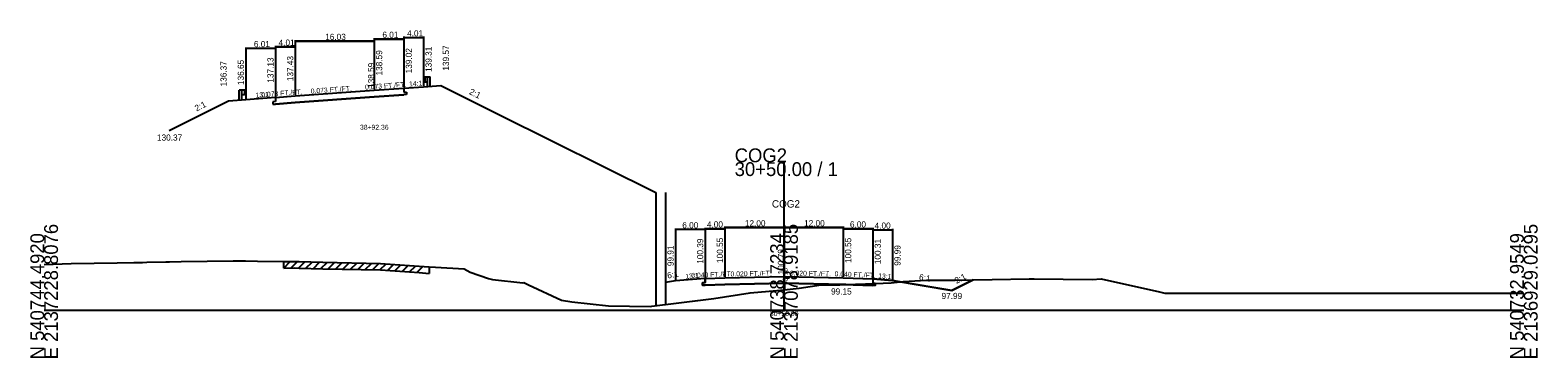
# Model space of a CAD drawing. Extents: x -13397 to 2303, y -10 to 39059.
# Drawn here: x 997.2 to 1302.8, y 990.3 to 1056.8 of the extents above; entities that cross this region are included whole.
import ezdxf

# ---------------------------------------------------------------- set-up
doc = ezdxf.new("R2010")
doc.units = 0
for name, color, linetype in [('Level 20', 7, 'Continuous'), ('Level 5', 7, 'Continuous'), ('Level 53', 7, 'Continuous'), ('Level 54', 7, 'Continuous'), ('Level 55', 7, 'Continuous'), ('Level 7', 7, 'Continuous'), ('RD_GPK_XS_Cell', 7, 'Continuous'), ('RD_XS_EwShp', 7, 'Continuous'), ('RD_XS_ExGround', 7, 'Continuous'), ('RD_XS_ExPaveRet', 7, 'Continuous'), ('RD_XS_MedBWall', 7, 'Continuous'), ('RD_XS_Pave', 7, 'Continuous'), ('RD_XS_TX_Baseline', 7, 'Continuous'), ('RD_XS_TX_Elev_EX', 7, 'Continuous'), ('RD_XS_TX_Elev_PR', 7, 'Continuous'), ('RD_XS_TX_Station', 7, 'Continuous')]:
    doc.layers.add(name, color=color, linetype=linetype)

msp = doc.modelspace()

# ---------------------------------------------------------------- linework, layer by layer
at = {"layer": 'Level 20'}
for p, q in [((1050.89, 1054.74), (1050.89, 1043.63)), ((1050.89, 1054.74), (1050.89, 1043.63)), ((1050.89, 1054.74), (1050.89, 1043.63)), ((1050.89, 1054.74), (1050.89, 1043.63)), ((1066.92, 1055.17), (1066.92, 1044.79)), ((1066.92, 1055.17), (1066.92, 1044.79)), ((1066.92, 1055.17), (1066.92, 1044.79)), ((1066.92, 1054.97), (1072.93, 1054.97)), ((1072.93, 1054.97), (1066.92, 1054.97)), ((1072.93, 1054.97), (1066.92, 1054.97)), ((1066.92, 1054.74), (1066.92, 1044.79)), ((1066.92, 1054.74), (1066.92, 1044.79)), ((1066.92, 1054.74), (1066.92, 1044.79)), ((1066.92, 1054.74), (1066.92, 1044.79)), ((1072.93, 1055.46), (1072.93, 1045.22)), ((1072.93, 1055.26), (1076.93, 1055.26)), ((1072.93, 1055.17), (1072.93, 1045.22)), ((1072.93, 1055.17), (1072.93, 1045.22)), ((1072.93, 1055.17), (1072.93, 1045.22)), ((1076.93, 1055.46), (1076.93, 1045.51)), ((1040.87, 1053.28), (1040.87, 1042.85)), ((1046.88, 1053.08), (1040.87, 1053.08)), ((1046.88, 1053.58), (1046.88, 1043.33)), ((1046.88, 1053.58), (1046.88, 1043.33)), ((1046.88, 1053.58), (1046.88, 1043.33)), ((1046.88, 1053.38), (1050.89, 1053.38)), ((1046.88, 1053.38), (1050.89, 1053.38)), ((1050.89, 1053.38), (1046.88, 1053.38)), ((1046.88, 1053.28), (1046.88, 1043.33)), ((1050.89, 1054.54), (1066.92, 1054.54)), ((1050.89, 1054.54), (1066.92, 1054.54)), ((1066.92, 1054.54), (1050.89, 1054.54)), ((1066.92, 1054.54), (1050.89, 1054.54)), ((1050.89, 1053.58), (1050.89, 1043.63)), ((1050.89, 1053.58), (1050.89, 1043.63)), ((1050.89, 1053.58), (1050.89, 1043.63)), ((1076.93, 1045.31), (1080.44, 1045.57)), ((1076.96, 1047.13), (1077.07, 1047.22)), ((1076.96, 1047.03), (1077.07, 1046.94)), ((1076.96, 1046.6), (1077.07, 1046.69)), ((1076.96, 1046.5), (1077.07, 1046.41)), ((1077.09, 1047.23), (1077.16, 1047.24)), ((1077.09, 1046.89), (1077.09, 1046.74)), ((1077.09, 1046.4), (1077.16, 1046.39)), ((1077.16, 1047.3), (1077.16, 1046.33)), ((1077.16, 1047.3), (1077.72, 1047.3)), ((1077.16, 1046.33), (1077.72, 1046.33)), ((1077.72, 1045.31), (1077.72, 1047.3)), ((1077.72, 1047.3), (1078.27, 1047.3)), ((1078.27, 1045.31), (1078.27, 1047.3)), ((1080.44, 1045.57), (1092.46, 1039.57)), ((1037.36, 1042.37), (1025.34, 1036.37)), ((1040.87, 1042.65), (1037.36, 1042.37)), ((1039.53, 1042.65), (1039.53, 1044.64)), ((1040.09, 1044.64), (1039.53, 1044.64)), ((1040.09, 1042.65), (1040.09, 1044.64)), ((1040.64, 1044.64), (1040.09, 1044.64)), ((1040.64, 1043.67), (1040.09, 1043.67)), ((1040.64, 1044.64), (1040.64, 1043.67)), ((1040.72, 1044.57), (1040.64, 1044.58)), ((1040.72, 1043.74), (1040.64, 1043.73)), ((1040.71, 1044.23), (1040.71, 1044.08)), ((1040.84, 1044.47), (1040.73, 1044.56)), ((1040.84, 1044.37), (1040.73, 1044.28)), ((1040.84, 1043.94), (1040.73, 1044.03)), ((1040.84, 1043.84), (1040.73, 1043.75)), ((1046.88, 1043.13), (1040.87, 1042.65)), ((1046.88, 1043.13), (1050.89, 1043.43)), ((1046.88, 1043.13), (1046.88, 1042.3)), ((1050.89, 1043.43), (1066.92, 1044.59)), ((1066.92, 1043.26), (1050.89, 1042.09)), ((1066.92, 1043.26), (1050.89, 1042.09)), ((1050.89, 1042.09), (1066.92, 1043.26)), ((1050.89, 1042.09), (1066.92, 1043.26)), ((1066.92, 1044.59), (1072.93, 1045.02)), ((1072.93, 1043.69), (1066.92, 1043.26)), ((1066.92, 1043.26), (1072.93, 1043.69)), ((1066.92, 1043.26), (1072.93, 1043.69)), ((1072.93, 1045.02), (1076.93, 1045.31)), ((1072.93, 1045.02), (1072.93, 1044.19)), ((1072.93, 1044.19), (1073.43, 1044.23)), ((1073.43, 1043.73), (1072.93, 1043.69)), ((1073.43, 1044.23), (1073.43, 1043.73)), ((1046.88, 1042.3), (1046.38, 1042.27)), ((1046.38, 1042.27), (1046.38, 1041.77)), ((1046.38, 1041.77), (1046.88, 1041.8)), ((1050.89, 1042.09), (1046.88, 1041.8)), ((1050.89, 1042.09), (1046.88, 1041.8)), ((1046.88, 1041.8), (1050.89, 1042.09)), ((1092.46, 1039.57), (1124, 1023.83))]:
    msp.add_line(p, q, dxfattribs=at)
for centre, radius, start, end in [((1077, 1047.08), 0.0651, 129.0336, 230.9663), ((1077, 1046.55), 0.0651, 129.0336, 230.9663), ((1077.02, 1046.74), 0.0651, 302.9895, 0), ((1077.09, 1047.2), 0.026, 90, 129.0505), ((1077.02, 1046.89), 0.0651, 0, 45), ((1077.09, 1046.43), 0.026, 230.9496, 270), ((1040.78, 1044.23), 0.0651, 135, 180), ((1040.78, 1044.08), 0.0651, 180, 237.0105), ((1040.72, 1044.54), 0.026, 50.9495, 90), ((1040.72, 1043.77), 0.026, 270, 309.0504), ((1040.8, 1044.42), 0.0651, 309.0337, 50.9664), ((1040.8, 1043.89), 0.0651, 309.0337, 50.9664)]:
    msp.add_arc(centre, radius, start, end, dxfattribs=at)
at = {"layer": 'Level 5'}
for p, q in [((1134, 1006.39), (1134, 1005.56)), ((1168, 1006.31), (1168, 1005.48)), ((1134, 1005.56), (1133.5, 1005.54)), ((1133.5, 1005.54), (1133.5, 1005.04)), ((1133.5, 1005.04), (1134, 1005.06)), ((1138, 1005.22), (1134, 1005.06)), ((1138, 1005.22), (1134, 1005.06)), ((1138, 1005.22), (1134, 1005.06)), ((1134, 1005.06), (1138, 1005.22)), ((1150, 1005.46), (1138, 1005.22)), ((1150, 1005.46), (1138, 1005.22)), ((1150, 1005.46), (1138, 1005.22)), ((1138, 1005.22), (1150, 1005.46)), ((1138, 1005.22), (1150, 1005.46)), ((1162, 1005.22), (1150, 1005.46)), ((1162, 1005.22), (1150, 1005.46)), ((1150, 1005.46), (1162, 1005.22)), ((1150, 1005.46), (1162, 1005.22)), ((1150, 1005.46), (1162, 1005.22)), ((1168, 1004.98), (1162, 1005.22)), ((1162, 1005.22), (1168, 1004.98)), ((1162, 1005.22), (1168, 1004.98)), ((1162, 1005.22), (1168, 1004.98)), ((1168, 1005.48), (1168.5, 1005.46)), ((1168.5, 1004.96), (1168, 1004.98)), ((1168.5, 1005.46), (1168.5, 1004.96))]:
    msp.add_line(p, q, dxfattribs=at)
at = {"layer": 'Level 54'}
for p, q in [((1128, 1016.54), (1128, 1006.11)), ((1134, 1016.34), (1128, 1016.34)), ((1134, 1016.7), (1134, 1006.59)), ((1134, 1016.7), (1134, 1006.59)), ((1134, 1016.7), (1134, 1006.59)), ((1134, 1016.7), (1134, 1006.59)), ((1134, 1016.54), (1134, 1006.59)), ((1134, 1016.5), (1138, 1016.5)), ((1134, 1016.5), (1138, 1016.5)), ((1134, 1016.5), (1138, 1016.5)), ((1138, 1016.5), (1134, 1016.5)), ((1138, 1016.94), (1138, 1006.75)), ((1138, 1016.94), (1138, 1006.75)), ((1138, 1016.94), (1138, 1006.75)), ((1138, 1016.94), (1138, 1006.75)), ((1138, 1016.94), (1138, 1006.75)), ((1138, 1016.74), (1150, 1016.74)), ((1138, 1016.74), (1150, 1016.74)), ((1138, 1016.74), (1150, 1016.74)), ((1150, 1016.74), (1138, 1016.74)), ((1150, 1016.74), (1138, 1016.74)), ((1138, 1016.7), (1138, 1006.75)), ((1138, 1016.7), (1138, 1006.75)), ((1138, 1016.7), (1138, 1006.75)), ((1138, 1016.7), (1138, 1006.75)), ((1150, 1016.94), (1150, 1006.99)), ((1150, 1016.94), (1150, 1006.99)), ((1150, 1016.94), (1150, 1006.99)), ((1150, 1016.94), (1150, 1006.99)), ((1150, 1016.94), (1150, 1006.99)), ((1150, 1016.94), (1150, 1006.99)), ((1150, 1016.94), (1150, 1006.99)), ((1150, 1016.94), (1150, 1006.99)), ((1150, 1016.94), (1150, 1006.99)), ((1150, 1016.94), (1150, 1006.99)), ((1150, 1016.74), (1162, 1016.74)), ((1150, 1016.74), (1162, 1016.74)), ((1162, 1016.74), (1150, 1016.74)), ((1162, 1016.74), (1150, 1016.74)), ((1162, 1016.74), (1150, 1016.74)), ((1162, 1016.94), (1162, 1006.75)), ((1162, 1016.94), (1162, 1006.75)), ((1162, 1016.94), (1162, 1006.75)), ((1162, 1016.94), (1162, 1006.75)), ((1162, 1016.94), (1162, 1006.75)), ((1162, 1016.7), (1162, 1006.75)), ((1162, 1016.7), (1162, 1006.75)), ((1162, 1016.7), (1162, 1006.75)), ((1162, 1016.7), (1162, 1006.75)), ((1162, 1016.5), (1168, 1016.5)), ((1168, 1016.5), (1162, 1016.5)), ((1168, 1016.5), (1162, 1016.5)), ((1168, 1016.5), (1162, 1016.5)), ((1168, 1016.7), (1168, 1006.51)), ((1168, 1016.7), (1168, 1006.51)), ((1168, 1016.7), (1168, 1006.51)), ((1168, 1016.7), (1168, 1006.51)), ((1168, 1016.46), (1168, 1006.51)), ((1168, 1016.26), (1172, 1016.26)), ((1172, 1016.46), (1172, 1006.19))]:
    msp.add_line(p, q, dxfattribs=at)
at = {"layer": 'Level 7'}
for p, q in [((1128, 1005.91), (1126, 1005.58)), ((1134, 1006.39), (1128, 1005.91)), ((1168, 1006.31), (1172, 1005.99)), ((1172, 1005.99), (1184, 1003.99)), ((1184, 1003.99), (1188.32, 1006.15)), ((1126, 1005.58), (1126, 1001.12))]:
    msp.add_line(p, q, dxfattribs=at)
at = {"layer": 'RD_GPK_XS_Cell'}
for p, q in [((1150, 1000), (1150, 1029.99)), ((1000, 1000), (1150, 1000)), ((1150, 1000), (1300, 1000))]:
    msp.add_line(p, q, dxfattribs=at)
at = {"layer": 'RD_XS_EwShp'}
for points in [[(1148.56, 1003.96), (1150, 1004.1), (1153.07, 1004.42), (1157.51, 1005.13), (1161.34, 1005.15), (1162.56, 1005.19), (1162, 1005.22), (1150, 1005.46), (1138, 1005.22), (1134, 1005.06), (1133.5, 1005.04), (1133.5, 1005.54), (1134, 1005.56), (1134, 1006.39), (1128, 1005.91), (1126, 1005.58), (1126, 1001.12), (1135.78, 1002.35), (1143.15, 1003.48)], [(1168.5, 1005.46), (1168.5, 1005.4), (1171.72, 1005.53), (1173.52, 1005.74), (1172, 1005.99), (1168, 1006.31), (1168, 1005.48)], [(1178.88, 1006.07), (1184.73, 1006.09), (1188.32, 1006.15), (1184, 1003.99), (1173.52, 1005.74), (1174.13, 1005.81)], [(1168.47, 1005.4), (1168.5, 1005.4), (1168.5, 1004.96), (1168, 1004.98), (1162.56, 1005.19)]]:
    msp.add_lwpolyline(points, close=True, dxfattribs=at)
at = {"layer": 'RD_XS_ExGround'}
for p, q in [((1000, 1009.26), (1005.46, 1009.47)), ((1005.46, 1009.47), (1014.78, 1009.59)), ((1014.78, 1009.59), (1018.19, 1009.65)), ((1018.19, 1009.65), (1019.92, 1009.68)), ((1019.92, 1009.68), (1020.83, 1009.71)), ((1020.83, 1009.71), (1024.7, 1009.76)), ((1024.7, 1009.76), (1025.38, 1009.78)), ((1025.38, 1009.78), (1027.79, 1009.84)), ((1027.79, 1009.84), (1038.33, 1010)), ((1038.33, 1010), (1040.85, 1009.99)), ((1040.85, 1009.99), (1043.26, 1009.92)), ((1043.26, 1009.92), (1048.58, 1009.83)), ((1048.58, 1009.83), (1050.7, 1009.84)), ((1050.7, 1009.84), (1051.7, 1009.83)), ((1051.7, 1009.83), (1056.52, 1009.69)), ((1056.52, 1009.69), (1068.2, 1009.43)), ((1068.2, 1009.43), (1076.03, 1008.89)), ((1076.03, 1008.89), (1078.09, 1008.75)), ((1078.09, 1008.75), (1079.31, 1008.68)), ((1079.31, 1008.68), (1085.13, 1008.36)), ((1085.13, 1008.36), (1086.37, 1007.68)), ((1086.37, 1007.68), (1090.11, 1006.4)), ((1090.11, 1006.4), (1090.88, 1006.2)), ((1090.88, 1006.2), (1097.06, 1005.5)), ((1171.72, 1005.53), (1174.13, 1005.81)), ((1174.13, 1005.81), (1178.88, 1006.07)), ((1178.88, 1006.07), (1184.73, 1006.09)), ((1184.73, 1006.09), (1199.69, 1006.34)), ((1199.69, 1006.34), (1200.74, 1006.34)), ((1200.74, 1006.34), (1212.48, 1006.21)), ((1212.48, 1006.21), (1214.28, 1006.35)), ((1214.28, 1006.35), (1226.15, 1003.71)), ((1097.06, 1005.5), (1097.23, 1005.56)), ((1097.23, 1005.56), (1098.17, 1005.11)), ((1098.17, 1005.11), (1104.86, 1002)), ((1135.78, 1002.35), (1143.15, 1003.48)), ((1143.15, 1003.48), (1148.56, 1003.96)), ((1148.56, 1003.96), (1150, 1004.1)), ((1150, 1004.1), (1153.07, 1004.42)), ((1153.07, 1004.42), (1157.51, 1005.13)), ((1157.51, 1005.13), (1161.34, 1005.15)), ((1161.34, 1005.15), (1168.47, 1005.4)), ((1168.47, 1005.4), (1171.72, 1005.53)), ((1226.15, 1003.71), (1227.23, 1003.44)), ((1227.23, 1003.44), (1227.69, 1003.44)), ((1227.69, 1003.44), (1228.56, 1003.44)), ((1228.56, 1003.44), (1232.73, 1003.44)), ((1232.73, 1003.44), (1233.6, 1003.44)), ((1233.6, 1003.44), (1261.41, 1003.44)), ((1261.41, 1003.44), (1262.44, 1003.44)), ((1262.44, 1003.44), (1270.99, 1003.44)), ((1270.99, 1003.44), (1276.35, 1003.44)), ((1276.35, 1003.44), (1300, 1003.44)), ((1104.86, 1002), (1107.01, 1001.7)), ((1107.01, 1001.7), (1114.42, 1000.86)), ((1114.42, 1000.86), (1122.93, 1000.73)), ((1122.93, 1000.73), (1123.23, 1000.77)), ((1123.23, 1000.77), (1135.78, 1002.35))]:
    msp.add_line(p, q, dxfattribs=at)
at = {"layer": 'RD_XS_ExPaveRet'}
for p, q in [((1048.58, 1008.53), (1049.88, 1009.84)), ((1048.58, 1008.53), (1048.58, 1009.83)), ((1050.08, 1008.54), (1051.38, 1009.83)), ((1051.58, 1008.53), (1052.85, 1009.79)), ((1053.08, 1008.49), (1054.35, 1009.75)), ((1054.58, 1008.45), (1055.85, 1009.71)), ((1056.08, 1008.4), (1057.35, 1009.67)), ((1057.58, 1008.37), (1058.86, 1009.64)), ((1059.08, 1008.33), (1060.36, 1009.61)), ((1060.58, 1008.3), (1061.86, 1009.57)), ((1062.08, 1008.27), (1063.36, 1009.54)), ((1063.58, 1008.23), (1064.86, 1009.51)), ((1065.08, 1008.2), (1066.36, 1009.47)), ((1066.58, 1008.17), (1067.86, 1009.44)), ((1068.08, 1008.13), (1069.31, 1009.36)), ((1069.58, 1008.04), (1070.8, 1009.25)), ((1071.08, 1007.93), (1072.3, 1009.15)), ((1072.58, 1007.83), (1073.8, 1009.05)), ((1074.08, 1007.73), (1075.3, 1008.94)), ((1075.58, 1007.62), (1076.8, 1008.84)), ((1048.58, 1008.53), (1050.7, 1008.54)), ((1050.7, 1008.54), (1051.7, 1008.53)), ((1051.7, 1008.53), (1056.52, 1008.39)), ((1056.52, 1008.39), (1068.2, 1008.13)), ((1068.2, 1008.13), (1076.03, 1007.59)), ((1076.03, 1007.59), (1078.09, 1007.45)), ((1078.09, 1008.75), (1078.09, 1007.45))]:
    msp.add_line(p, q, dxfattribs=at)
at = {"layer": 'RD_XS_MedBWall'}
for p, q in [((1124, 1023.83), (1124, 1000.86)), ((1126, 1023.83), (1126, 1005.58))]:
    msp.add_line(p, q, dxfattribs=at)
at = {"layer": 'RD_XS_Pave'}
for p, q in [((1134, 1006.39), (1138, 1006.55)), ((1138, 1006.55), (1150, 1006.79)), ((1150, 1006.79), (1162, 1006.55)), ((1162, 1006.55), (1168, 1006.31))]:
    msp.add_line(p, q, dxfattribs=at)

# ---------------------------------------------------------------- texts
at = {"layer": 'Level 20'}
for s, height, p in [('6.01', 1.25, (1042.52, 1053.33)), ('4.01', 1.25, (1047.53, 1053.63)), ('4.01', 1.25, (1047.53, 1053.63)), ('4.01', 1.25, (1047.53, 1053.63)), ('16.03', 1.25, (1056.98, 1054.79)), ('16.03', 1.25, (1056.98, 1054.79)), ('16.03', 1.25, (1056.98, 1054.79)), ('16.03', 1.25, (1056.98, 1054.79)), ('6.01', 1.25, (1068.57, 1055.22)), ('6.01', 1.25, (1068.57, 1055.22)), ('6.01', 1.25, (1068.57, 1055.22)), ('4.01', 1.25, (1073.58, 1055.51)), ('38+92.36', 1, (1064.03, 1036.59)), ('130.37', 1.25, (1022.87, 1034.37))]:
    msp.add_text(s, height=height, dxfattribs=at).set_placement(p)
for s, height, rotation, p in [('138.59', 1.25, 90, (1068.54, 1047.59)), ('138.59', 1.25, 90, (1068.54, 1047.59)), ('139.02', 1.25, 90, (1074.55, 1048.02)), ('139.31', 1.25, 90, (1078.56, 1048.31)), ('139.57', 1.25, 90, (1082.07, 1048.57)), ('136.37', 1.25, 90, (1036.99, 1045.37)), ('136.65', 1.25, 90, (1040.49, 1045.65)), ('137.13', 1.25, 90, (1046.5, 1046.13)), ('137.43', 1.25, 90, (1050.51, 1046.43)), ('137.43', 1.25, 90, (1050.51, 1046.43)), (' 138.59', 1.25, 90, (1066.92, 1044.59)), ('0.073 FT./FT.', 1, 4.1503, (1054.07, 1043.91)), ('0.073 FT./FT.', 1, 4.1503, (1054.07, 1043.91)), ('0.073 FT./FT.', 1, 4.1503, (1054.07, 1043.91)), ('0.073 FT./FT.', 1, 4.1503, (1054.07, 1043.91)), ('0.073 FT./FT.', 1, 4.1497, (1065.09, 1044.71)), ('0.073 FT./FT.', 1, 4.1497, (1065.09, 1044.71)), ('0.073 FT./FT.', 1, 4.1497, (1065.09, 1044.71)), ('14:1', 1, 4.1425, (1074.01, 1045.35)), ('13:1', 1, 4.5656, (1042.9, 1043.07)), ('0.073 FT./FT.', 1, 4.1509, (1044.05, 1043.18)), ('0.073 FT./FT.', 1, 4.1509, (1044.05, 1043.18)), ('0.073 FT./FT.', 1, 4.1509, (1044.05, 1043.18)), ('2:1', 1.25, 333.475, (1086.06, 1043.88)), ('2:1', 1.25, 26.5231, (1030.9, 1040.27))]:
    msp.add_text(s, height=height, rotation=rotation, dxfattribs=at).set_placement(p)
at = {"layer": 'Level 53'}
for s, rotation, p in [('99.91', 90, (1127.62, 1008.91)), ('100.39', 90, (1133.62, 1009.39)), ('100.55', 90, (1137.63, 1009.55)), ('100.55', 90, (1137.63, 1009.55)), ('100.55', 90, (1137.63, 1009.55)), ('100.55', 90, (1163.63, 1009.55)), ('100.55', 90, (1163.63, 1009.55)), ('100.55', 90, (1163.63, 1009.55)), ('100.31', 90, (1169.63, 1009.31)), ('99.99', 90, (1173.63, 1008.99)), ('6:1', 9.4623, (1126.42, 1006.39)), ('6:1', 350.5377, (1177.3, 1006.12))]:
    msp.add_text(s, height=1.25, rotation=rotation, dxfattribs=at).set_placement(p)
for s, p in [('99.15', (1159.54, 1003.15)), ('97.99', (1181.94, 1002.24))]:
    msp.add_text(s, height=1.25, dxfattribs=at).set_placement(p)
at = {"layer": 'Level 54'}
for s, p in [('4.00', (1134.37, 1016.75)), ('4.00', (1134.37, 1016.75)), ('4.00', (1134.37, 1016.75)), ('4.00', (1134.37, 1016.75)), ('12.00', (1142.07, 1016.99)), ('12.00', (1142.07, 1016.99)), ('12.00', (1142.07, 1016.99)), ('12.00', (1142.07, 1016.99)), ('12.00', (1142.07, 1016.99)), ('12.00', (1154.07, 1016.99)), ('12.00', (1154.07, 1016.99)), ('12.00', (1154.07, 1016.99)), ('12.00', (1154.07, 1016.99)), ('12.00', (1154.07, 1016.99)), ('6.00', (1163.37, 1016.75)), ('6.00', (1163.37, 1016.75)), ('6.00', (1163.37, 1016.75)), ('6.00', (1163.37, 1016.75)), ('6.00', (1129.37, 1016.59)), ('4.00', (1168.37, 1016.51))]:
    msp.add_text(s, height=1.25, dxfattribs=at).set_placement(p)
at = {"layer": 'Level 55'}
for s, height, rotation, p in [('13:1', 1, 4.5739, (1130.03, 1006.32)), ('0.040 FT./FT.', 1, 2.2906, (1131.22, 1006.53)), ('0.040 FT./FT.', 1, 2.2906, (1131.22, 1006.53)), ('0.040 FT./FT.', 1, 2.2906, (1131.22, 1006.53)), ('0.040 FT./FT.', 1, 2.2906, (1131.22, 1006.53)), ('0.020 FT./FT.', 1, 1.1458, (1139.17, 1006.82)), ('0.020 FT./FT.', 1, 1.1458, (1139.17, 1006.82)), ('0.020 FT./FT.', 1, 1.1458, (1139.17, 1006.82)), ('0.020 FT./FT.', 1, 1.1458, (1139.17, 1006.82)), ('0.020 FT./FT.', 1, 1.1458, (1139.17, 1006.82)), ('0.020 FT./FT.', 1, 358.8542, (1151.18, 1007.02)), ('0.020 FT./FT.', 1, 358.8542, (1151.18, 1007.02)), ('0.020 FT./FT.', 1, 358.8542, (1151.18, 1007.02)), ('0.020 FT./FT.', 1, 358.8542, (1151.18, 1007.02)), ('0.020 FT./FT.', 1, 358.8542, (1151.18, 1007.02)), ('0.040 FT./FT.', 1, 357.7094, (1160.24, 1006.87)), ('0.040 FT./FT.', 1, 357.7094, (1160.24, 1006.87)), ('0.040 FT./FT.', 1, 357.7094, (1160.24, 1006.87)), ('0.040 FT./FT.', 1, 357.7094, (1160.24, 1006.87)), ('13:1', 1, 355.4261, (1169.07, 1006.48)), ('2:1', 1.25, 26.5651, (1184.98, 1005.32))]:
    msp.add_text(s, height=height, rotation=rotation, dxfattribs=at).set_placement(p)
at = {"layer": 'RD_GPK_XS_Cell'}
for s, p in [('COG2', (1140, 1029.99)), ('30+50.00 / 1', (1140, 1027.19))]:
    msp.add_text(s, height=2.8, dxfattribs=at).set_placement(p)
for s, p in [('N 540744.4920', (1000, 990)), ('E 2137228.8076', (1002.8, 990)), ('N 540738.7234', (1150, 990)), ('E 2137078.9185', (1152.8, 990)), ('N 540732.9549', (1300, 990)), ('E 2136929.0295', (1302.8, 990))]:
    msp.add_text(s, height=2.8, rotation=90, dxfattribs=at).set_placement(p)
at = {"layer": 'RD_XS_TX_Baseline'}
msp.add_text('COG2', height=1.5, dxfattribs=at).set_placement((1147.55, 1020.79))
at = {"layer": 'RD_XS_TX_Elev_EX'}
msp.add_text('98.10', height=1, rotation=90, dxfattribs=at).set_placement((1150.75, 1005.1))
at = {"layer": 'RD_XS_TX_Elev_PR'}
msp.add_text(' 100.79', height=1.25, rotation=90, dxfattribs=at).set_placement((1150, 1006.79))
at = {"layer": 'RD_XS_TX_Station'}
msp.add_text('30+50.00', height=1, dxfattribs=at).set_placement((1147.14, 998.79))

doc.saveas('drawing.dxf')
